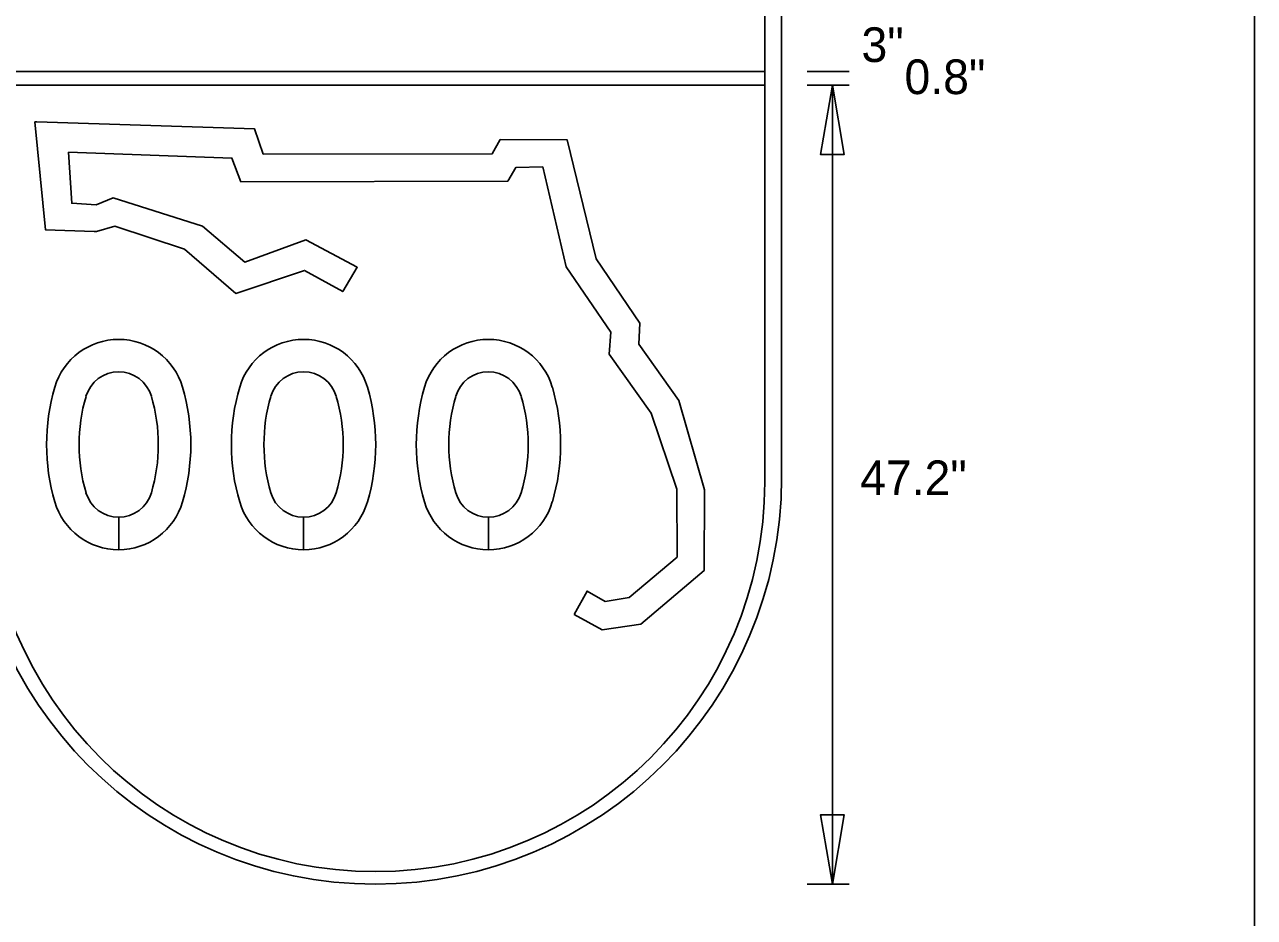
# Model space of a CAD drawing. Extents: x 0 to 770, y 0 to 495.
# Drawn here: x 260.9 to 385, y 206.1 to 296.2 of the extents above; entities that cross this region are included whole.
import ezdxf

# ---------------------------------------------------------------- set-up
doc = ezdxf.new("R2010")
doc.units = 0
for name, color, linetype in [('Default', 7, 'Continuous'), ('Dimension', 7, 'Continuous'), ('GSBWFill', 7, 'Continuous'), ('GSColorFill', 7, 'Continuous'), ('GSDims', 7, 'Continuous'), ('GSOutline', 7, 'Continuous'), ('IndexDetail_0', 7, 'Continuous'), ('SheetLines_dp', 7, 'Continuous'), ('TextStructures', 7, 'Continuous')]:
    doc.layers.add(name, color=color, linetype=linetype)

msp = doc.modelspace()

# ---------------------------------------------------------------- linework, layer by layer
at = {"layer": 'Default'}
for points in [[(262.09, 286.42), (261.9, 286.42)], [(261.9, 286.42), (262.98, 275.52), (267.89, 275.37)], [(316.35, 236.7), (319.15, 235.15), (323.05, 235.74), (329.45, 241.14), (329.49, 249.27), (326.9, 258.3), (322.87, 264), (322.95, 266.12), (318.55, 272.59), (315.64, 284.59), (308.87, 284.63), (308.07, 283.2), (284.96, 283.17), (284.06, 285.72), (262.09, 286.42)], [(268.13, 275.37), (269.97, 275.91), (277.01, 273.56), (282.17, 269.11), (289.12, 271.43), (292.97, 269.3), (294.44, 271.74), (289.24, 274.5), (283.09, 272.27), (278.81, 275.88), (269.79, 278.75), (268.08, 278.05), (265.62, 278.21), (265.3, 283.36), (281.79, 282.77), (282.7, 280.38), (309.64, 280.45)], [(309.64, 280.45), (310.45, 281.83), (313.16, 281.87), (315.53, 271.8), (320.04, 265.19), (319.88, 262.98), (324.1, 257.01), (326.69, 249.36)], [(267.89, 275.37), (268.13, 275.37)], [(326.69, 249.36), (326.74, 242.48)], [(326.74, 242.48), (321.9, 238.41), (319.47, 238.01), (317.64, 239.06), (316.35, 236.7)]]:
    msp.add_lwpolyline(points, dxfattribs=at)
at = {"layer": 'Dimension'}
for points in [[(342.4, 290.14), (341.21, 283.12), (343.59, 283.12)], [(342.4, 209.48), (343.59, 216.5), (341.21, 216.5)]]:
    msp.add_lwpolyline(points, close=True, dxfattribs=at)
at = {"layer": 'GSBWFill'}
for p, q in [((335.57, 300.48), (335.57, 250.1)), ((337.28, 250.27), (337.28, 300.48)), ((335.57, 291.51), (256.96, 291.51)), ((335.57, 290.14), (335.57, 291.51)), ((256.96, 290.14), (335.57, 290.14)), ((270.36, 246.52), (270.36, 243.24)), ((270.36, 243.24), (270.36, 246.52)), ((289.02, 246.52), (289.02, 243.24)), ((289.02, 243.24), (289.02, 246.52)), ((307.68, 246.52), (307.68, 243.24)), ((307.68, 243.24), (307.68, 246.52))]:
    msp.add_line(p, q, dxfattribs=at)
for centre, radius, start, end in [((270.36, 257.75), 6.72, 16.4025, 163.5975), ((289.02, 257.75), 6.72, 16.4025, 163.5975), ((307.68, 257.75), 6.72, 16.4025, 163.5975), ((270.36, 257.75), 3.44, 16.4025, 163.5975), ((289.02, 257.75), 3.44, 16.4025, 163.5975), ((307.68, 257.75), 3.44, 16.4025, 163.5975), ((283.59, 253.85), 20.51, 163.5975, 196.4025), ((257.13, 253.85), 20.51, 343.5975, 16.4025), ((302.25, 253.85), 20.51, 163.5975, 196.4025), ((275.79, 253.85), 20.51, 343.5975, 16.4025), ((320.91, 253.85), 20.51, 163.5975, 196.4025), ((294.46, 253.85), 20.51, 343.5975, 16.4025), ((283.59, 253.85), 17.23, 163.5975, 196.4025), ((257.13, 253.85), 17.23, 343.5975, 16.4025), ((302.25, 253.85), 17.23, 163.5975, 196.4025), ((275.79, 253.85), 17.23, 343.5975, 16.4025), ((320.91, 253.85), 17.23, 163.5975, 196.4025), ((294.46, 253.85), 17.23, 343.5975, 16.4025), ((270.36, 249.96), 3.44, 196.4025, 270), ((270.36, 249.96), 3.44, 270.0171, 343.5975), ((289.02, 249.96), 3.44, 196.4025, 270), ((289.02, 249.96), 3.44, 270.0171, 343.5975), ((307.68, 249.96), 3.44, 196.4025, 270), ((307.68, 249.96), 3.44, 270.0171, 343.5975), ((270.36, 249.96), 6.72, 196.4025, 270), ((270.36, 249.96), 6.72, 270.0087, 343.5975), ((289.02, 249.96), 6.72, 196.4025, 270), ((289.02, 249.96), 6.72, 270.0087, 343.5975), ((307.68, 249.96), 6.72, 196.4025, 270), ((307.68, 249.96), 6.72, 270.0087, 343.5975)]:
    msp.add_arc(centre, radius, start, end, dxfattribs=at)
at = {"layer": 'GSColorFill'}
for p, q in [((335.57, 291.51), (256.96, 291.51)), ((335.57, 290.14), (335.57, 291.51)), ((256.96, 290.14), (335.57, 290.14)), ((270.36, 246.52), (270.36, 243.24)), ((270.36, 243.24), (270.36, 246.52)), ((289.02, 246.52), (289.02, 243.24)), ((289.02, 243.24), (289.02, 246.52)), ((307.68, 246.52), (307.68, 243.24)), ((307.68, 243.24), (307.68, 246.52))]:
    msp.add_line(p, q, dxfattribs=at)
for centre, radius, start, end in [((270.36, 257.75), 6.72, 16.4025, 163.5975), ((289.02, 257.75), 6.72, 16.4025, 163.5975), ((307.68, 257.75), 6.72, 16.4025, 163.5975), ((270.36, 257.75), 3.44, 16.4025, 163.5975), ((289.02, 257.75), 3.44, 16.4025, 163.5975), ((307.68, 257.75), 3.44, 16.4025, 163.5975), ((283.59, 253.85), 20.51, 163.5975, 196.4025), ((257.13, 253.85), 20.51, 343.5975, 16.4025), ((302.25, 253.85), 20.51, 163.5975, 196.4025), ((275.79, 253.85), 20.51, 343.5975, 16.4025), ((320.91, 253.85), 20.51, 163.5975, 196.4025), ((294.46, 253.85), 20.51, 343.5975, 16.4025), ((283.59, 253.85), 17.23, 163.5975, 196.4025), ((257.13, 253.85), 17.23, 343.5975, 16.4025), ((302.25, 253.85), 17.23, 163.5975, 196.4025), ((275.79, 253.85), 17.23, 343.5975, 16.4025), ((320.91, 253.85), 17.23, 163.5975, 196.4025), ((294.46, 253.85), 17.23, 343.5975, 16.4025), ((270.36, 249.96), 3.44, 196.4025, 270), ((270.36, 249.96), 3.44, 270.0171, 343.5975), ((289.02, 249.96), 3.44, 196.4025, 270), ((289.02, 249.96), 3.44, 270.0171, 343.5975), ((307.68, 249.96), 3.44, 196.4025, 270), ((307.68, 249.96), 3.44, 270.0171, 343.5975), ((270.36, 249.96), 6.72, 196.4025, 270), ((270.36, 249.96), 6.72, 270.0087, 343.5975), ((289.02, 249.96), 6.72, 196.4025, 270), ((289.02, 249.96), 6.72, 270.0087, 343.5975), ((307.68, 249.96), 6.72, 196.4025, 270), ((307.68, 249.96), 6.72, 270.0087, 343.5975)]:
    msp.add_arc(centre, radius, start, end, dxfattribs=at)
at = {"layer": 'GSDims'}
for p, q in [((339.84, 291.51), (344.11, 291.51)), ((339.84, 291.51), (344.11, 291.51)), ((339.84, 290.14), (344.11, 290.14)), ((339.84, 290.14), (344.11, 290.14)), ((342.4, 209.48), (342.4, 290.14)), ((339.84, 209.48), (344.11, 209.48))]:
    msp.add_line(p, q, dxfattribs=at)
at = {"layer": 'GSOutline'}
for p, q in [((335.57, 291.51), (256.96, 291.51)), ((335.57, 290.14), (335.57, 291.51)), ((256.96, 290.14), (335.57, 290.14))]:
    msp.add_line(p, q, dxfattribs=at)
for centre, radius, start, end in [((270.36, 257.75), 6.72, 16.4025, 163.5975), ((289.02, 257.75), 6.72, 16.4025, 163.5975), ((307.68, 257.75), 6.72, 16.4025, 163.5975), ((270.36, 257.75), 3.44, 16.4025, 163.5975), ((289.02, 257.75), 3.44, 16.4025, 163.5975), ((307.68, 257.75), 3.44, 16.4025, 163.5975), ((283.59, 253.85), 20.51, 163.5975, 196.4025), ((257.13, 253.85), 20.51, 343.5975, 16.4025), ((302.25, 253.85), 20.51, 163.5975, 196.4025), ((275.79, 253.85), 20.51, 343.5975, 16.4025), ((320.91, 253.85), 20.51, 163.5975, 196.4025), ((294.46, 253.85), 20.51, 343.5975, 16.4025), ((283.59, 253.85), 17.23, 163.5975, 196.4025), ((257.13, 253.85), 17.23, 343.5975, 16.4025), ((302.25, 253.85), 17.23, 163.5975, 196.4025), ((275.79, 253.85), 17.23, 343.5975, 16.4025), ((320.91, 253.85), 17.23, 163.5975, 196.4025), ((294.46, 253.85), 17.23, 343.5975, 16.4025), ((270.36, 249.96), 3.44, 196.4025, 343.5975), ((289.02, 249.96), 3.44, 196.4025, 343.5975), ((307.68, 249.96), 3.44, 196.4025, 343.5975), ((270.36, 249.96), 6.72, 196.4025, 343.5975), ((289.02, 249.96), 6.72, 196.4025, 343.5975), ((307.68, 249.96), 6.72, 196.4025, 343.5975)]:
    msp.add_arc(centre, radius, start, end, dxfattribs=at)
at = {"layer": 'IndexDetail_0'}
for centre, radius, end in [((296.26, 250.5), 41.01, 360), ((296.27, 250.06), 39.3, 0)]:
    msp.add_arc(centre, radius, 180, end, dxfattribs=at)
at = {"layer": 'SheetLines_dp'}
msp.add_line((385, 0), (385, 495), dxfattribs=at)

# ---------------------------------------------------------------- texts
at = {"layer": 'TextStructures'}
for s, p in [('3"', (345.34, 292.46)), ('0.8"', (349.68, 289.22)), ('47.2"', (345.2, 248.75))]:
    msp.add_text(s, height=3.5, dxfattribs=at).set_placement(p)

doc.saveas('drawing.dxf')
